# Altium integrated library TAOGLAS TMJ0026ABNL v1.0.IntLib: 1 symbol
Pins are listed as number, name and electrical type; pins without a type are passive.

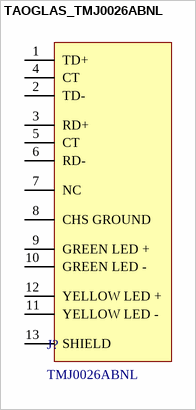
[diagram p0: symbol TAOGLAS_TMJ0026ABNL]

## TAOGLAS_TMJ0026ABNL
designator J?, comment TMJ0026ABNL
RJ45 connector with integrated magnetics 10/100Base-T Single Port Tab-DOWN with right angle THT mount and LEDs; ComponentLibStatus: Created; MFG: Taoglas; Temp_High: +85C; Temp_Low: -40C
footprint TAOGLAS_TMJ0026ABNL (RJ45 connector with integrated magnetics 10/100Base-T Single Port Tab-DOWN with right angle THT mount and LEDs)
pins: 1 TD+, 2 TD-, 3 RD+, 4 CT, 5 CT, 6 RD-, 7 NC, 8 CHS GROUND, 9 GREEN LED +, 10 GREEN LED -, 11 YELLOW LED -, 12 YELLOW LED +, 13 SHIELD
